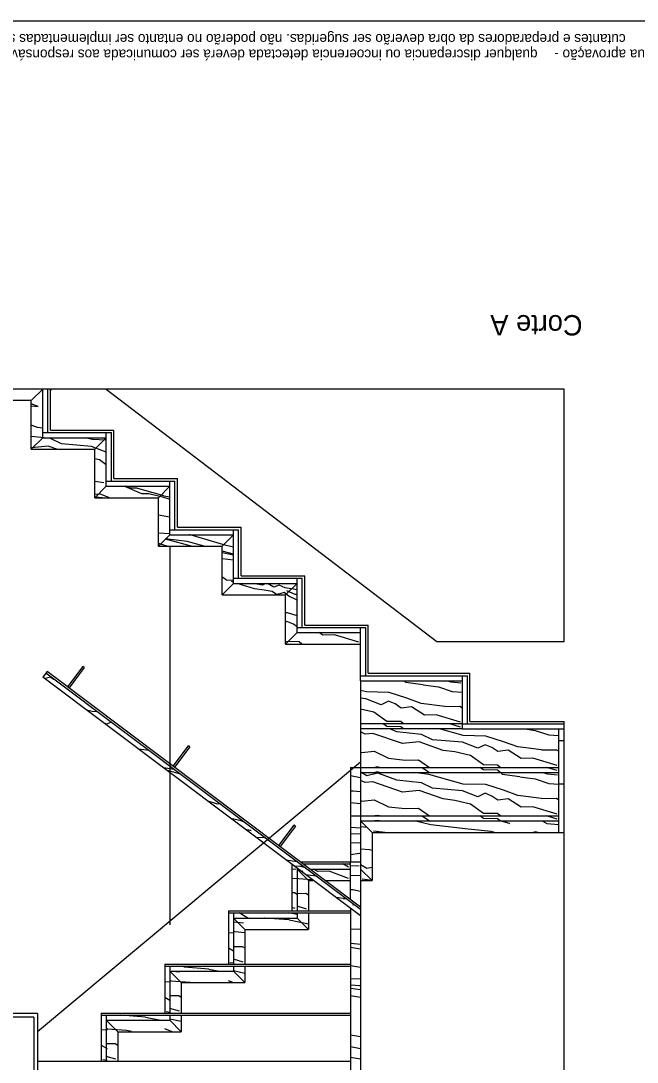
# Model space of a CAD drawing. Extents: x 1290.6 to 1307.2, y -290.6 to -281.7.
# Drawn here: x 1299.614 to 1302.037, y -286.298 to -282.201 of the extents above; entities that cross this region are included whole.
import ezdxf

# ---------------------------------------------------------------- set-up
doc = ezdxf.new("R2010")
doc.units = 0
for name, color, linetype in [('Level 1', 7, 'Continuous'), ('Level 13', 7, 'Continuous'), ('Level 2', 7, 'Continuous'), ('Level 31', 7, 'Continuous'), ('Level 4', 7, 'Continuous'), ('Level 60', 7, 'Continuous'), ('Level 62', 7, 'Continuous')]:
    doc.layers.add(name, color=color, linetype=linetype)

msp = doc.modelspace()

# ---------------------------------------------------------------- linework, layer by layer
at = {"layer": 'Level 1'}
for p, q in [((1301.7497, -283.64984), (1299.22246, -283.64984)), ((1299.6997, -283.84084), (1299.6997, -283.64984)), ((1299.7197, -283.82084), (1299.7197, -283.64984)), ((1299.7297, -283.81084), (1299.7297, -283.64984)), ((1299.94926, -283.64984), (1301.2498, -284.64284)), ((1301.7497, -284.64284), (1301.7497, -283.64984)), ((1299.7297, -283.81084), (1299.9797, -283.81084)), ((1299.9797, -284.00184), (1299.9797, -283.81084)), ((1299.6997, -283.82084), (1299.9697, -283.82084)), ((1299.6997, -283.84084), (1299.9497, -283.84084)), ((1299.9497, -284.03184), (1299.9497, -283.82084)), ((1299.9697, -284.01184), (1299.9697, -283.82084)), ((1299.9497, -284.01184), (1300.2197, -284.01184)), ((1299.9797, -284.00184), (1300.2297, -284.00184)), ((1300.1997, -284.22284), (1300.1997, -284.01184)), ((1300.2197, -284.20284), (1300.2197, -284.01184)), ((1300.2297, -284.19284), (1300.2297, -284.00184)), ((1299.9497, -284.03184), (1300.1997, -284.03184)), ((1300.1997, -284.20284), (1300.4697, -284.20284)), ((1300.1997, -284.22284), (1300.4497, -284.22284)), ((1300.2297, -284.19284), (1300.4797, -284.19284)), ((1300.4497, -284.41384), (1300.4497, -284.20284)), ((1300.4697, -284.39384), (1300.4697, -284.20284)), ((1300.4797, -284.38384), (1300.4797, -284.19284)), ((1300.4797, -284.38384), (1300.7297, -284.38384)), ((1300.7297, -284.57784), (1300.7297, -284.38384)), ((1300.4497, -284.39384), (1300.7197, -284.39384)), ((1300.4497, -284.41384), (1300.6997, -284.41384)), ((1300.6997, -284.60784), (1300.6997, -284.39384)), ((1300.7197, -284.58784), (1300.7197, -284.39384)), ((1300.6997, -284.58784), (1300.9697, -284.58784)), ((1300.7297, -284.57784), (1300.9797, -284.57784)), ((1300.9497, -284.79784), (1300.9497, -284.58784)), ((1300.9697, -284.77784), (1300.9697, -284.58784)), ((1300.9797, -284.76784), (1300.9797, -284.57784)), ((1300.6997, -284.60784), (1300.9497, -284.60784)), ((1301.2498, -284.64284), (1301.7497, -284.64284)), ((1300.9497, -284.77784), (1301.3697, -284.77784)), ((1300.9497, -284.79784), (1301.3497, -284.79784)), ((1300.9797, -284.76784), (1301.3797, -284.76784)), ((1301.3497, -284.98684), (1301.3497, -284.77784)), ((1301.3697, -284.96684), (1301.3697, -284.77784)), ((1301.3797, -284.95684), (1301.3797, -284.76784)), ((1301.3797, -284.95684), (1301.7497, -284.95684)), ((1301.7497, -288.93984), (1301.7497, -284.95684)), ((1301.3497, -284.96684), (1301.7497, -284.96684)), ((1301.3497, -284.98684), (1301.7497, -284.98684)), ((1301.7297, -285.03184), (1301.7297, -284.98684)), ((1301.7297, -285.03184), (1301.7497, -285.03184)), ((1299.6797, -286.10584), (1299.22246, -286.10584)), ((1299.6797, -286.10584), (1299.6797, -286.50584)), ((1299.6647, -286.12084), (1299.22246, -286.12084)), ((1299.6647, -286.12084), (1299.6647, -286.43584))]:
    msp.add_line(p, q, dxfattribs=at)
at = {"layer": 'Level 13'}
for points in [[(1299.6547, -283.71531), (1299.68172, -283.71777), (1299.6547, -283.70704)], [(1299.6997, -283.80297), (1299.67947, -283.80006), (1299.6547, -283.79193)], [(1299.9497, -283.89801), (1299.8916, -283.87494), (1299.77365, -283.86533), (1299.73092, -283.84428), (1299.6547, -283.83607)], [(1299.9497, -283.8501), (1299.89409, -283.84853), (1299.86611, -283.84084)], [(1299.75455, -283.88584), (1299.72102, -283.8741), (1299.655, -283.88033), (1299.6547, -283.88023)], [(1299.9497, -283.94704), (1299.92262, -283.92762), (1299.9047, -283.92342)], [(1299.9047, -284.01188), (1299.94032, -284.01756)], [(1300.02182, -284.03184), (1300.08836, -284.06086), (1300.11676, -284.06037), (1300.17093, -284.07397)], [(1300.1756, -284.06929), (1300.09141, -284.04585), (1300.07024, -284.03912), (1300.04564, -284.03981), (1300.02447, -284.03184)], [(1299.96231, -284.07684), (1299.92729, -284.06294), (1299.9047, -284.06388)], [(1299.9047, -284.07274), (1299.9066, -284.07313), (1299.94751, -284.07684)], [(1300.17093, -284.07397), (1300.1997, -284.08234)], [(1300.1756, -284.06929), (1300.1997, -284.0729)], [(1300.1997, -284.15413), (1300.1547, -284.14604)], [(1300.1997, -284.21842), (1300.1547, -284.21689)], [(1300.4497, -284.27176), (1300.42136, -284.265), (1300.27971, -284.22312), (1300.27596, -284.22284)], [(1300.1547, -284.25636), (1300.16688, -284.25993), (1300.19163, -284.26784)], [(1300.33471, -284.26784), (1300.26726, -284.24868), (1300.18076, -284.23819), (1300.28719, -284.26784)], [(1300.4497, -284.29968), (1300.4047, -284.28764)], [(1300.4047, -284.29243), (1300.4497, -284.30178)], [(1300.4047, -284.31613), (1300.4497, -284.32098)], [(1300.4497, -284.40319), (1300.42182, -284.40086), (1300.40765, -284.39144), (1300.4047, -284.39229)], [(1300.4497, -284.40923), (1300.44205, -284.40684)], [(1300.6997, -284.47899), (1300.69736, -284.47925), (1300.66795, -284.46408), (1300.64853, -284.44942), (1300.6326, -284.45487), (1300.61904, -284.45793), (1300.60225, -284.44589), (1300.57083, -284.44061), (1300.53192, -284.43495), (1300.46443, -284.41384)], [(1300.57526, -284.41384), (1300.56366, -284.42156), (1300.52711, -284.41384)], [(1300.6997, -284.43937), (1300.65267, -284.43217), (1300.62968, -284.42107), (1300.60887, -284.42877), (1300.5839, -284.41384)], [(1300.6997, -284.45763), (1300.69256, -284.45783), (1300.65947, -284.44373)], [(1300.6997, -284.542), (1300.66209, -284.52986), (1300.6547, -284.52965)], [(1300.6997, -284.58467), (1300.68514, -284.57458), (1300.65998, -284.56386), (1300.6547, -284.5663)], [(1300.94244, -284.64558), (1300.84638, -284.61663), (1300.80098, -284.61818), (1300.78496, -284.60784)], [(1300.71859, -284.65284), (1300.70751, -284.6439), (1300.6547, -284.6431)], [(1299.74547, -284.79202), (1299.74299, -284.79181), (1299.72882, -284.78239), (1299.7104, -284.78771)], [(1301.19561, -284.81275), (1301.12652, -284.80341), (1301.12407, -284.79784)], [(1301.29275, -284.79784), (1301.30423, -284.80102), (1301.34422, -284.80489)], [(1301.28096, -284.8981), (1301.18733, -284.88603), (1301.13141, -284.86623), (1301.06209, -284.84386), (1300.97291, -284.84136), (1300.9497, -284.83498)], [(1301.19561, -284.81275), (1301.25597, -284.82138), (1301.30991, -284.8392), (1301.3497, -284.84218)], [(1301.34244, -284.95958), (1301.24638, -284.93063), (1301.20098, -284.93218), (1301.1501, -284.89935), (1301.10868, -284.90489), (1301.08514, -284.88858), (1301.05998, -284.87786), (1301.03034, -284.89155), (1300.97042, -284.86776), (1300.9497, -284.86607)], [(1299.91417, -284.91888), (1299.89409, -284.91831), (1299.87212, -284.91227)], [(1301.11859, -284.96684), (1301.10751, -284.9579), (1301.05251, -284.95707), (1301.00144, -284.92045), (1300.9497, -284.90831)], [(1301.28096, -284.8981), (1301.33931, -284.89749), (1301.3497, -284.90361)], [(1299.96927, -284.96031), (1299.95151, -284.96851), (1299.94174, -284.96463)], [(1301.49859, -285.13784), (1301.48751, -285.1289), (1301.43251, -285.12807), (1301.38144, -285.09145), (1301.3201, -285.07706), (1301.27432, -285.071), (1301.17984, -285.03793), (1301.11382, -285.04415), (1300.99817, -285.00434), (1300.96797, -285.00664), (1300.9497, -284.99793)], [(1301.11859, -284.98684), (1301.10751, -284.9779), (1301.05251, -284.97707), (1301.03824, -284.96684)], [(1301.72244, -285.13058), (1301.62638, -285.10163), (1301.58098, -285.10318), (1301.5301, -285.07035), (1301.48868, -285.07589), (1301.46514, -285.05958), (1301.43998, -285.04886), (1301.41034, -285.06255), (1301.35042, -285.03876), (1301.23247, -285.02915), (1301.18974, -285.0081), (1301.09259, -284.99763), (1301.06393, -284.98684)], [(1301.66096, -285.0691), (1301.56733, -285.05703), (1301.51141, -285.03723), (1301.44209, -285.01486), (1301.35291, -285.01236), (1301.26007, -284.98684)], [(1301.34244, -284.97958), (1301.30017, -284.96684)], [(1301.59722, -284.98684), (1301.63597, -284.99238), (1301.68991, -285.0102), (1301.7297, -285.01318)], [(1300.11717, -285.07153), (1300.07722, -285.06651)], [(1300.9497, -285.07761), (1300.95453, -285.07987), (1301.00354, -285.07472), (1301.05984, -285.10212), (1301.12461, -285.1091), (1301.17761, -285.10793), (1301.22076, -285.13784)], [(1301.66096, -285.0691), (1301.71931, -285.06849), (1301.7297, -285.07461)], [(1300.1756, -285.13907), (1300.17259, -285.13823)], [(1300.1756, -285.13907), (1300.21479, -285.14494)], [(1300.18561, -285.14802), (1300.23987, -285.1638)], [(1301.72244, -285.32158), (1301.62638, -285.29263), (1301.58098, -285.29418), (1301.5301, -285.26135), (1301.48868, -285.26689), (1301.46514, -285.25058), (1301.43998, -285.23986), (1301.41034, -285.25355), (1301.35042, -285.22976), (1301.23247, -285.22015), (1301.18974, -285.1991), (1301.09259, -285.18863), (1301.01729, -285.16028), (1300.97426, -285.17142), (1300.95202, -285.15784)], [(1301.02415, -285.13784), (1301.01414, -285.13587), (1301.00495, -285.13784)], [(1301.02415, -285.15784), (1301.01414, -285.15587), (1301.00495, -285.15784)], [(1301.66096, -285.2601), (1301.56733, -285.24803), (1301.51141, -285.22823), (1301.44209, -285.20586), (1301.35291, -285.20336), (1301.21845, -285.1664), (1301.15889, -285.15784)], [(1301.19191, -285.13784), (1301.22076, -285.15784)], [(1301.49859, -285.15784), (1301.48751, -285.1489), (1301.43251, -285.14807), (1301.41824, -285.13784)], [(1301.57561, -285.17475), (1301.50652, -285.16541), (1301.50319, -285.15784)], [(1301.66553, -285.15784), (1301.68423, -285.16302), (1301.72422, -285.16689)], [(1301.72244, -285.15058), (1301.68017, -285.13784)], [(1300.9097, -285.17046), (1300.9497, -285.17771)], [(1301.49859, -285.32884), (1301.48751, -285.3199), (1301.43251, -285.31907), (1301.38144, -285.28245), (1301.3201, -285.26806), (1301.27432, -285.262), (1301.17984, -285.22893), (1301.11382, -285.23515), (1300.99817, -285.19534), (1300.96797, -285.19764), (1300.9497, -285.18893)], [(1301.57561, -285.17475), (1301.63597, -285.18338), (1301.68991, -285.2012), (1301.7297, -285.20418)], [(1300.9097, -285.2296), (1300.92101, -285.2299), (1300.9497, -285.23305)], [(1300.39864, -285.2832), (1300.38259, -285.28177), (1300.34985, -285.27153)], [(1300.9497, -285.28198), (1300.9097, -285.27733)], [(1300.9497, -285.26861), (1300.95453, -285.27087), (1301.00354, -285.26572), (1301.05984, -285.29312), (1301.12461, -285.3001), (1301.17761, -285.29893), (1301.22076, -285.32884)], [(1301.66096, -285.2601), (1301.71931, -285.25949), (1301.7297, -285.26561)], [(1301.02415, -285.32884), (1301.01414, -285.32687), (1301.00495, -285.32884)], [(1301.19191, -285.32884), (1301.22076, -285.34884)], [(1301.49859, -285.34884), (1301.48751, -285.3399), (1301.43251, -285.33907), (1301.41824, -285.32884)], [(1301.72244, -285.34158), (1301.68017, -285.32884)], [(1300.49144, -285.35298), (1300.48062, -285.34891), (1300.43981, -285.33918)], [(1300.9756, -285.37474), (1300.9497, -285.3721)], [(1301.02415, -285.34884), (1301.01414, -285.34687), (1301.00495, -285.34884)], [(1301.47591, -285.39384), (1301.4624, -285.39085), (1301.37224, -285.38052), (1301.22611, -285.36405), (1301.15973, -285.34884)], [(1301.38797, -285.34884), (1301.38455, -285.34912), (1301.3837, -285.34884)], [(1301.5106, -285.34884), (1301.5347, -285.35841), (1301.4977, -285.34884)], [(1301.66341, -285.34884), (1301.68248, -285.35812), (1301.7297, -285.36321)], [(1300.49554, -285.38109), (1300.51733, -285.38562)], [(1300.51995, -285.38824), (1300.49683, -285.38206)], [(1300.53785, -285.41291), (1300.57194, -285.41353)], [(1300.9097, -285.37338), (1300.9497, -285.37547)], [(1300.9497, -285.40007), (1300.9097, -285.40109)], [(1301.00058, -285.38796), (1301.05635, -285.39384)], [(1301.64679, -285.39384), (1301.63678, -285.39187), (1301.62759, -285.39384)], [(1300.9097, -285.43292), (1300.94353, -285.43466), (1300.9497, -285.43332)], [(1300.9497, -285.47686), (1300.94558, -285.47644), (1300.9097, -285.48172)], [(1300.9497, -285.45818), (1300.98408, -285.46075), (1300.9947, -285.46337)], [(1300.69895, -285.50904), (1300.65718, -285.50264)], [(1300.72864, -285.53136), (1300.70874, -285.52715), (1300.69256, -285.52761), (1300.68753, -285.52547)], [(1300.90244, -285.53058), (1300.88017, -285.51784)], [(1300.9097, -285.52424), (1300.94422, -285.52565)], [(1300.9497, -285.51961), (1300.97443, -285.53418), (1300.9947, -285.53051)], [(1300.6797, -285.53676), (1300.6943, -285.53817)], [(1300.6797, -285.57395), (1300.69977, -285.57546)], [(1300.6997, -285.53707), (1300.70325, -285.53741)], [(1300.6997, -285.57348), (1300.70491, -285.5752), (1300.75728, -285.57912)], [(1300.72362, -285.55261), (1300.72091, -285.54645), (1300.71613, -285.54697)], [(1300.77422, -285.56564), (1300.73366, -285.56015)], [(1300.90244, -285.57558), (1300.82638, -285.54663), (1300.78098, -285.54818), (1300.76496, -285.53784)], [(1300.9097, -285.56144), (1300.9497, -285.56294)], [(1300.95558, -285.57696), (1300.9947, -285.58108)], [(1300.9097, -285.61835), (1300.91931, -285.61825), (1300.9497, -285.62437)], [(1300.6797, -285.63087), (1300.68939, -285.63077), (1300.69978, -285.63689)], [(1300.6997, -285.63385), (1300.73431, -285.63349), (1300.7447, -285.63961)], [(1300.88096, -285.65388), (1300.8536, -285.65035)], [(1300.88096, -285.65388), (1300.89142, -285.65377)], [(1300.69252, -285.69286), (1300.6797, -285.689)], [(1300.73744, -285.69558), (1300.6997, -285.68421)], [(1300.92244, -285.68034), (1300.91844, -285.67914)], [(1300.50604, -285.73084), (1300.47259, -285.71084)], [(1300.66829, -285.73825), (1300.57168, -285.73122), (1300.57104, -285.73084)], [(1300.6997, -285.71696), (1300.66633, -285.71084)], [(1300.66829, -285.73825), (1300.7447, -285.7541)], [(1300.7447, -285.71329), (1300.73133, -285.71084)], [(1300.91207, -285.71223), (1300.9097, -285.71152)], [(1300.94244, -285.71536), (1300.93844, -285.71416)], [(1300.4497, -285.74607), (1300.48922, -285.74989)], [(1300.4497, -285.78248), (1300.45491, -285.7842), (1300.4947, -285.78718)], [(1300.9097, -285.77327), (1300.94631, -285.77422), (1300.9497, -285.77514)], [(1300.4297, -285.78718), (1300.4497, -285.78867)], [(1300.4297, -285.84861), (1300.4497, -285.86039)], [(1300.4497, -285.84285), (1300.48431, -285.84249), (1300.4947, -285.84861)], [(1300.9097, -285.82917), (1300.91284, -285.82964), (1300.9497, -285.83412)], [(1300.9097, -285.84583), (1300.9497, -285.85165)], [(1300.48744, -285.90458), (1300.4497, -285.89321)], [(1300.2077, -285.93984), (1300.23922, -285.94289)], [(1300.35329, -285.93125), (1300.25668, -285.92422), (1300.24935, -285.91984)], [(1300.35329, -285.93125), (1300.39471, -285.93984)], [(1300.43558, -285.90596), (1300.4497, -285.90745)], [(1300.4497, -285.93776), (1300.4947, -285.9471)], [(1300.9497, -285.92544), (1300.9097, -285.91899)], [(1300.1797, -285.98018), (1300.1997, -285.98167)], [(1300.1997, -285.97548), (1300.20491, -285.9772), (1300.27908, -285.98275), (1300.28755, -285.98484)], [(1300.4478, -285.98484), (1300.42965, -285.97801)], [(1300.9497, -285.97107), (1300.9097, -285.96957)], [(1300.9497, -285.99831), (1300.94609, -285.99728), (1300.9097, -285.99529)], [(1300.9097, -286.00633), (1300.9497, -286.0119)], [(1300.1797, -286.04161), (1300.1997, -286.05339)], [(1300.1997, -286.03585), (1300.23431, -286.03549), (1300.2447, -286.04161)], [(1300.9097, -286.03538), (1300.9497, -286.04177)], [(1300.18558, -286.09896), (1300.1997, -286.10045)], [(1300.23744, -286.09758), (1300.1997, -286.08621)], [(1300.10329, -286.12025), (1300.00668, -286.11322), (1300.00604, -286.11284)], [(1300.10329, -286.12025), (1300.164, -286.13284)], [(1300.1997, -286.12676), (1300.2447, -286.1361)], [(1299.9297, -286.16918), (1299.95259, -286.17089)], [(1299.9497, -286.16448), (1299.95491, -286.1662), (1300.02908, -286.17175), (1300.04826, -286.17648)], [(1300.20842, -286.17784), (1300.17965, -286.16701)], [(1299.9297, -286.23061), (1299.95259, -286.2441)], [(1299.9497, -286.22485), (1299.98431, -286.22449), (1299.9947, -286.23061)], [(1300.9497, -286.19879), (1300.9097, -286.19222)], [(1300.9497, -286.24553), (1300.9097, -286.238)], [(1299.93558, -286.28796), (1299.95259, -286.28975)], [(1299.98744, -286.28658), (1299.9497, -286.27521)], [(1300.9497, -286.28608), (1300.9097, -286.2792)]]:
    msp.add_lwpolyline(points, dxfattribs=at)
at = {"layer": 'Level 2'}
for p, q in [((1299.6547, -283.69484), (1299.6997, -283.64984)), ((1299.7333, -283.64984), (1299.7297, -283.65344)), ((1299.6547, -283.69484), (1299.3197, -283.69484)), ((1299.6547, -283.88584), (1299.6547, -283.69484)), ((1299.6547, -283.88584), (1299.6997, -283.84084)), ((1299.9047, -283.88584), (1299.9497, -283.84084)), ((1299.6547, -283.88584), (1299.9047, -283.88584)), ((1299.9047, -284.07684), (1299.9047, -283.88584)), ((1299.9047, -284.07684), (1299.9497, -284.03184)), ((1300.1547, -284.07684), (1300.1997, -284.03184)), ((1299.9047, -284.07684), (1300.1547, -284.07684)), ((1300.1547, -284.26784), (1300.1547, -284.07684)), ((1300.1547, -284.26784), (1300.1997, -284.22284)), ((1300.4047, -284.26784), (1300.4497, -284.22284)), ((1300.1547, -284.26784), (1300.4047, -284.26784)), ((1300.4047, -284.45884), (1300.4047, -284.26784)), ((1300.4047, -284.45884), (1300.4497, -284.41384)), ((1300.6547, -284.45884), (1300.6997, -284.41384)), ((1300.4047, -284.45884), (1300.6547, -284.45884)), ((1300.6547, -284.65284), (1300.6547, -284.45884)), ((1300.6547, -284.65284), (1300.6997, -284.60784)), ((1300.6547, -284.65284), (1300.9497, -284.65284)), ((1299.8569, -284.7407), (1299.79678, -284.8206)), ((1299.8633, -284.74551), (1299.80318, -284.82541)), ((1299.8633, -284.74551), (1299.8569, -284.7407)), ((1299.71686, -284.7605), (1299.70004, -284.78287)), ((1300.9497, -285.72262), (1299.70004, -284.78287)), ((1300.9497, -285.6976), (1299.71206, -284.76689)), ((1300.9497, -285.6876), (1299.71686, -284.7605)), ((1300.9497, -284.79784), (1300.9497, -285.53784)), ((1301.7497, -284.95684), (1301.7497, -284.95684)), ((1301.3497, -284.96684), (1300.9497, -284.96684)), ((1301.3497, -284.98684), (1300.9497, -284.98684)), ((1300.27198, -285.05282), (1300.21186, -285.13272)), ((1300.27836, -285.05763), (1300.21824, -285.13753)), ((1300.27836, -285.05763), (1300.27198, -285.05282)), ((1300.9097, -285.13784), (1300.9097, -285.50984)), ((1300.9097, -285.13784), (1301.7297, -285.13784)), ((1300.9497, -285.15784), (1301.7297, -285.15784)), ((1300.9097, -285.32884), (1300.9497, -285.32884)), ((1300.9497, -285.32884), (1301.7297, -285.32884)), ((1300.68704, -285.36496), (1300.62692, -285.44486)), ((1300.69342, -285.36977), (1300.6333, -285.44967)), ((1300.69342, -285.36977), (1300.68704, -285.36496)), ((1300.9497, -285.34884), (1301.7297, -285.34884)), ((1300.6797, -285.51958), (1300.6797, -285.70284)), ((1300.6997, -285.53462), (1300.6997, -285.70284)), ((1300.71332, -285.50984), (1300.9497, -285.50984)), ((1300.72396, -285.51784), (1300.9097, -285.51784)), ((1300.9097, -285.65752), (1300.9097, -285.50984)), ((1300.9497, -285.50984), (1300.9497, -286.48308)), ((1300.6997, -285.53784), (1300.70226, -285.53784)), ((1300.75055, -285.53784), (1300.9097, -285.53784)), ((1300.9097, -285.69254), (1300.9097, -286.51267)), ((1300.4297, -285.70284), (1300.4297, -285.91184)), ((1300.4297, -285.70284), (1300.9097, -285.70284)), ((1300.4297, -285.71084), (1300.9097, -285.71084)), ((1300.4497, -285.71084), (1300.4497, -285.91184)), ((1300.4497, -285.73084), (1300.6997, -285.73084)), ((1300.6997, -285.71084), (1300.6997, -285.73084)), ((1300.1797, -285.91184), (1300.1797, -286.10484)), ((1300.1797, -285.91184), (1300.9097, -285.91184)), ((1300.1797, -285.91984), (1300.4497, -285.91984)), ((1300.1997, -285.91984), (1300.9097, -285.91984)), ((1300.1997, -285.91984), (1300.1997, -286.10484)), ((1300.1997, -285.93984), (1300.4497, -285.93984)), ((1300.4497, -285.91984), (1300.4497, -285.93984)), ((1299.9297, -286.10484), (1299.9297, -286.29384)), ((1299.9297, -286.10484), (1300.9097, -286.10484)), ((1299.9297, -286.11284), (1300.1997, -286.11284)), ((1299.9497, -286.11284), (1300.9097, -286.11284)), ((1299.9497, -286.11284), (1299.9497, -286.29384)), ((1299.9497, -286.13284), (1300.1997, -286.13284)), ((1300.1997, -286.11284), (1300.1997, -286.13284)), ((1299.6797, -286.29384), (1300.9097, -286.29384))]:
    msp.add_line(p, q, dxfattribs=at)
at = {"layer": 'Level 31'}
for p, q in [((1301.7297, -285.39384), (1301.7297, -285.03184)), ((1301.7297, -285.20284), (1301.7497, -285.20284)), ((1300.9947, -285.39384), (1300.9497, -285.34884)), ((1300.9947, -285.39384), (1300.9947, -285.58284)), ((1300.9947, -285.39384), (1301.7497, -285.39384)), ((1300.7447, -285.58284), (1300.6997, -285.53784)), ((1300.9947, -285.58284), (1300.9497, -285.53784)), ((1300.7447, -285.58284), (1300.7447, -285.70284)), ((1300.7447, -285.58284), (1300.7621, -285.58284)), ((1300.80866, -285.58284), (1300.9097, -285.58284)), ((1300.9497, -285.58284), (1300.9947, -285.58284)), ((1300.4947, -285.77584), (1300.4497, -285.73084)), ((1300.7447, -285.77584), (1300.6997, -285.73084)), ((1300.7447, -285.71084), (1300.7447, -285.77584)), ((1300.4947, -285.77584), (1300.7447, -285.77584)), ((1300.4947, -285.77584), (1300.4947, -285.91184)), ((1300.2447, -285.98484), (1300.1997, -285.93984)), ((1300.4947, -285.98484), (1300.4497, -285.93984)), ((1300.4947, -285.91984), (1300.4947, -285.98484)), ((1300.2447, -285.98484), (1300.4947, -285.98484)), ((1300.2447, -285.98484), (1300.2447, -286.10484)), ((1299.9947, -286.17784), (1299.9497, -286.13284)), ((1300.2447, -286.17784), (1300.1997, -286.13284)), ((1300.2447, -286.11284), (1300.2447, -286.17784)), ((1299.9947, -286.17784), (1300.2447, -286.17784)), ((1299.9947, -286.17784), (1299.9947, -286.29384))]:
    msp.add_line(p, q, dxfattribs=at)
at = {"layer": 'Level 4'}
for p, q in [((1300.1997, -284.26784), (1300.1997, -285.75745)), ((1300.9497, -285.11733), (1299.6797, -286.17905))]:
    msp.add_line(p, q, dxfattribs=at)
at = {"layer": 'Level 62'}
msp.add_lwpolyline([(1307.19356, -282.2006), (1307.19356, -290.6006), (1295.59396, -290.6006), (1295.59396, -282.2006)], close=True, dxfattribs=at)

# ---------------------------------------------------------------- texts
at = {"layer": 'Level 60'}
for s, height, rotation, p in [('cutantes e preparadores da obra deverão ser sugeridas. não poderão no entanto ser implementadas sem o consentimento expresso dos responsáveis pela arquitectura', 0.0399996, 180, (1301.99195, -282.2526)), ('qualquer discrepancia ou incoerencia detectada deverá ser comunicada aos responsáveis pela arquitectura com o objectivo de ser analizada e corrigida -', 0.0399996, 180, (1301.64535, -282.3136)), ('os desenhos de preparação de obra deverão ser fornecidos ao projectista para sua aprovação -', 0.0399996, 180, (1303.98275, -282.3136)), ('Corte A', 0.08, 180.00001, (1301.82233, -283.35838)), ('Corte A', 0.08, 180.00001, (1301.82234, -283.35838))]:
    msp.add_text(s, height=height, rotation=rotation, dxfattribs=at).set_placement(p)

doc.saveas('drawing.dxf')
